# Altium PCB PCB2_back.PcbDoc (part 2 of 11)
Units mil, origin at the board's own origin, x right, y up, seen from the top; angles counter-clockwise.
Board outline 6299 x 3937 mil, 4 copper layers (TopLayer, GROUND, VCC, BottomLayer); 290 components, 470 nets, 2252 pads, 825 vias.
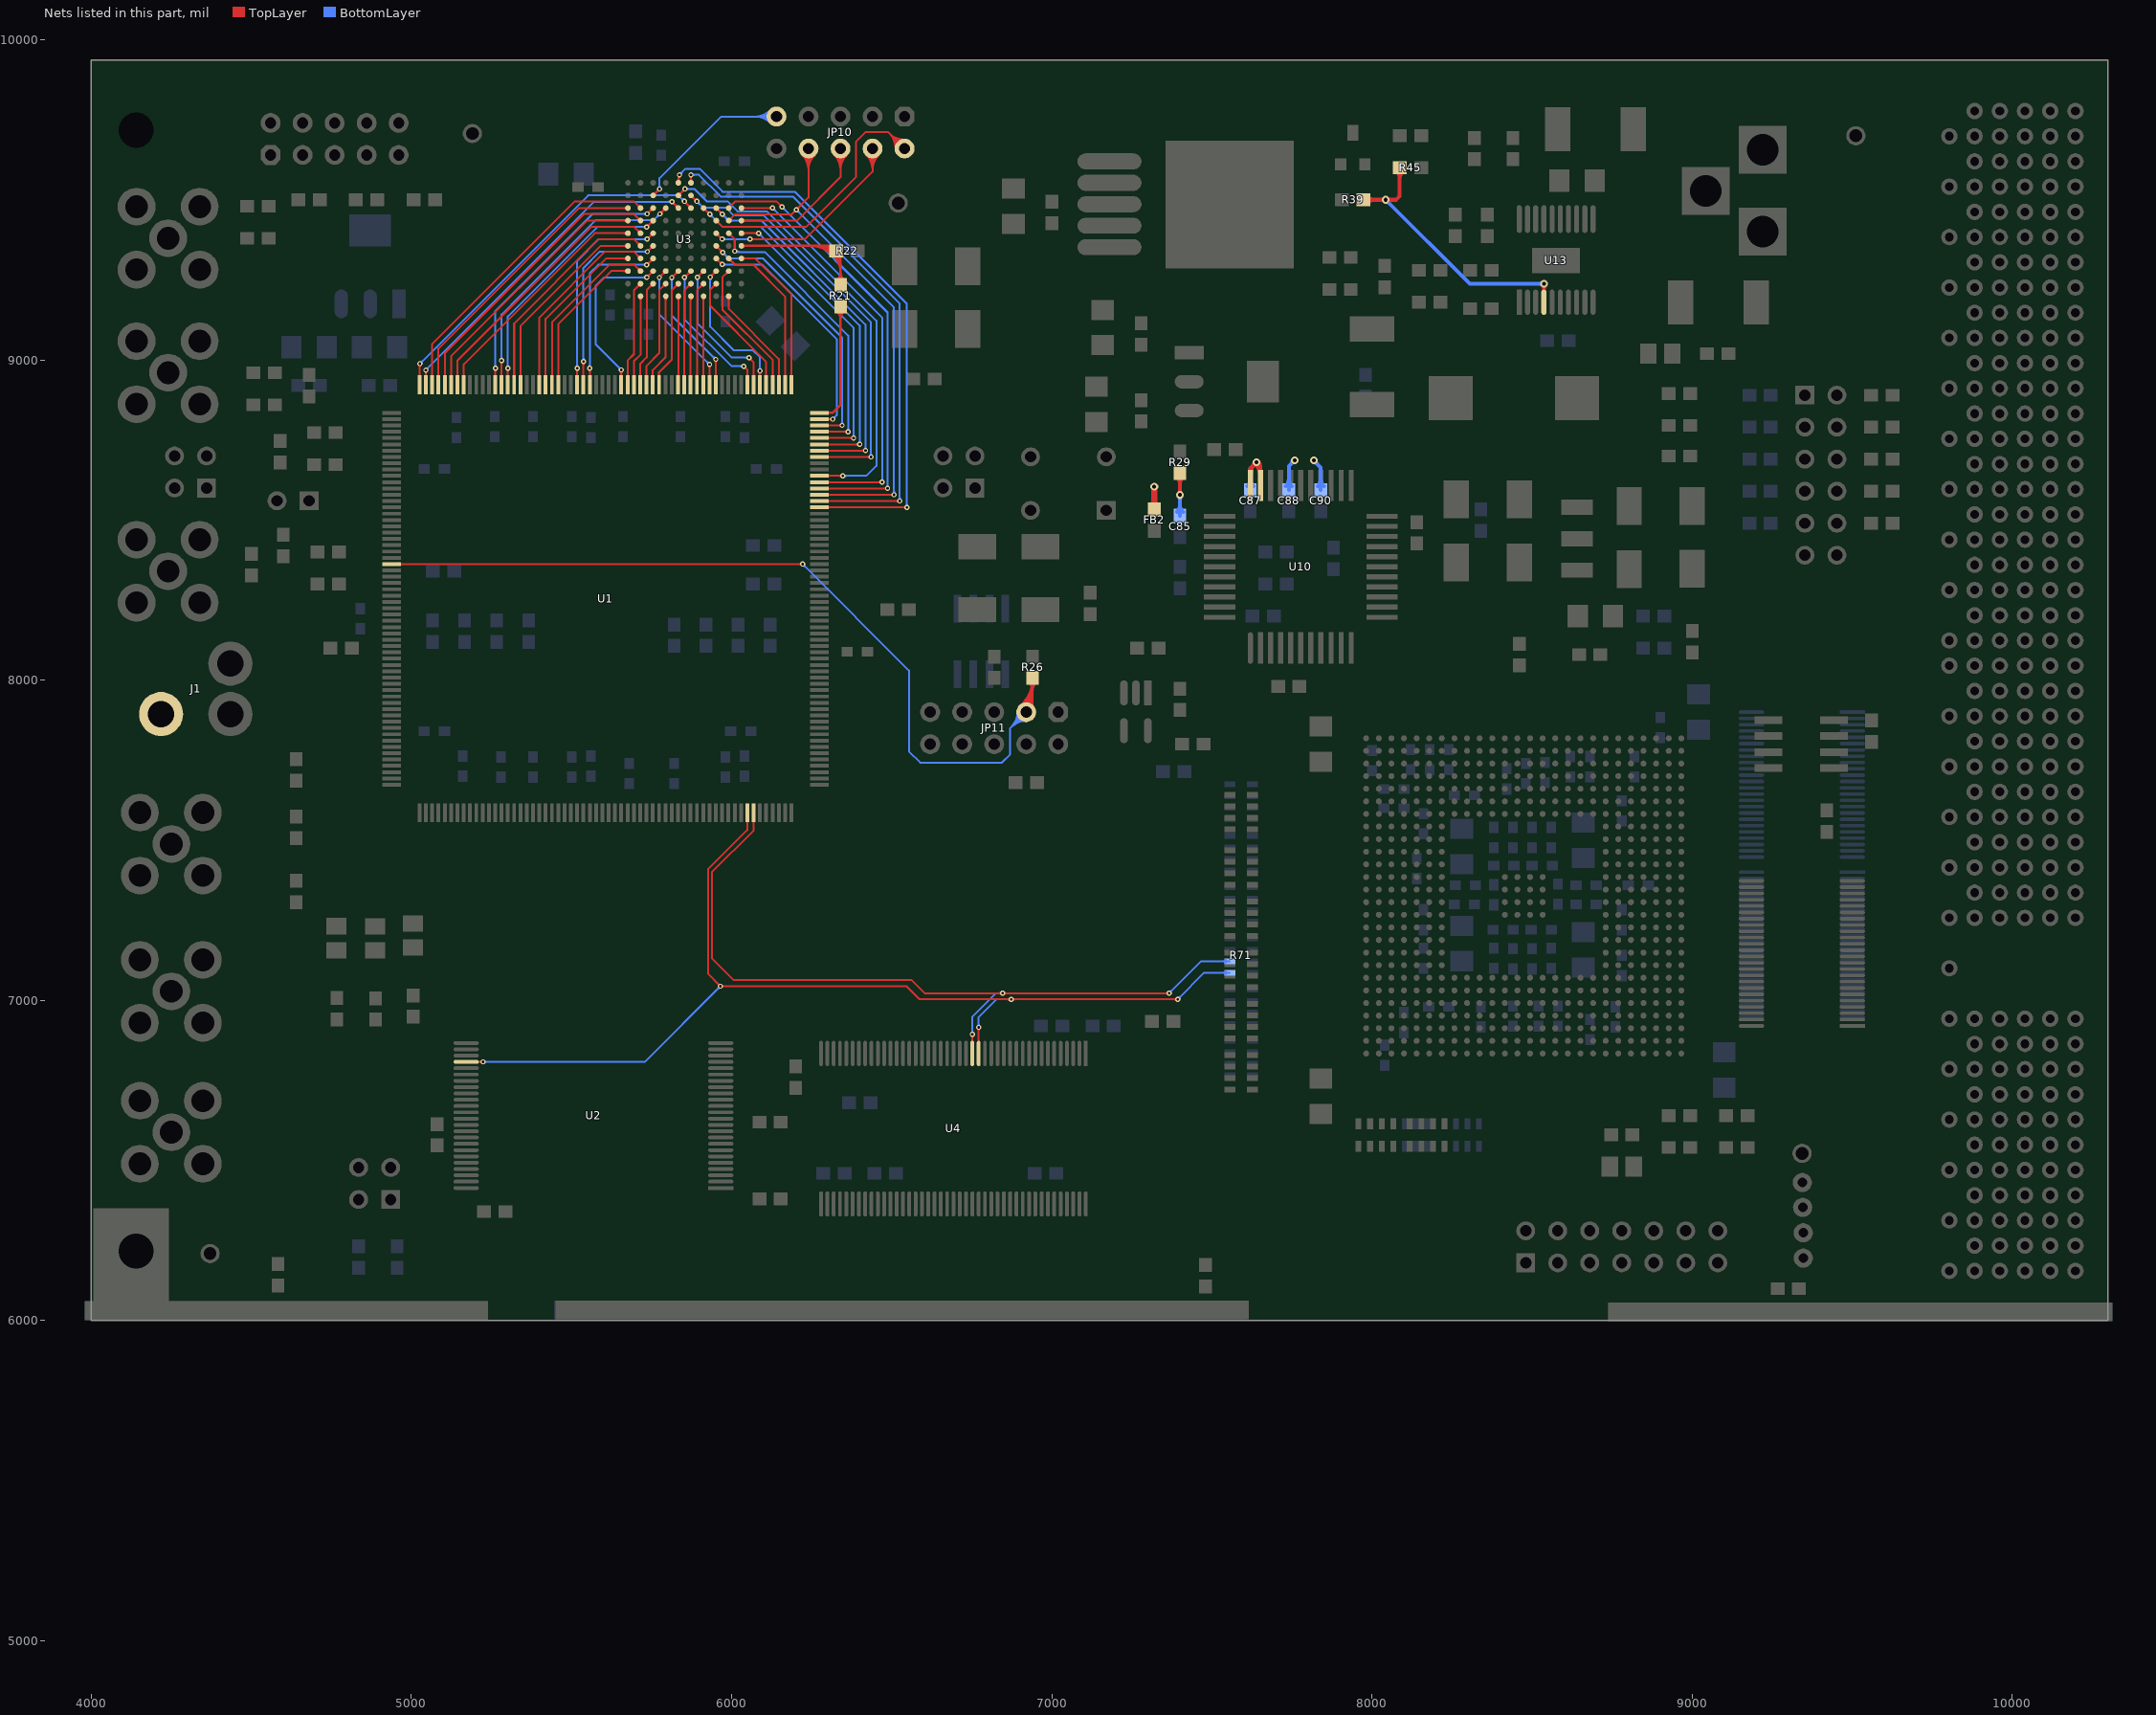
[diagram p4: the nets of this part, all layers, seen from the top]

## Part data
C1 C2 C3 C4 C5 C6 C7 C8 C9 C10 C11 C15 C16 C17 C18 C19 C22 C24 C25 C26 C27 C28 C32 C33 C34 C36 C37 C39 C40 C41 C42 C44 C45 C46 C47 C48 C49 C51 C52 C53 C54 C56 C57 C58 C59 C60 C61 C62 C63 C64 C65 C66 C67 C68 C69 C70 C71 C73 C74 C75 C76 C77 C79 C80 C81 C82 C83 C84 C85 C86 C87 C88 C89 C90 C91 C92 C93 C94 C95 C96 C97 C98 C99 C100 C101 C102 C103 C105 C107 C108 C109 C110 C111 C112 C113 C114 C115 C116 C117 C118 C119 C120 C121 C122 C123 C124 C125 C126 C127 C128 C129 C130 C131 C132 C133 C134 C136 C137 C139 C140 C141 C142 C143 C144 C145: "Capacitor"
C12 C13 C14 C23 C31 C35 C38 C43 C50 C72: "Polarized Capacitor (Radial)"
C20 C21 C29 C30 C55 C78 C104 C106 C135 C138 C146 C147: "Polarized Capacitor (Axial)"
DS1 DS2 DS3: "Typical RED, GREEN, YELLOW, AMBER GaAs LED"
DS4 DS5: "Typical BLUE SiC LED"
FB1 FB2 FB3 FB4 FB5 FB6 FB7 FB8: library part Inductor, "Inductor"
J1: "RCA Connector"
J2: library part "Header 7X2", "Header, 7-Pin, Dual row"
J4: "Z-Pack 2mm Hard Metric Type A 110 Position Female PCB Mount Connector"
J5: "Z-Pack 2mm Hard Metric Type B 110 Position Female Daughter Card Connector"
JP1 JP2 JP3 JP4 JP6 JP7 JP9: "Header, 2-Pin"
JP5 JP12: "Header, 2-Pin, Dual row"
JP8 JP10 JP11: library part "Header 5X2", "Header, 5-Pin, Dual row"
JP13: "Header, 6-Pin, Dual row"
L1: "Magnetic-Core Inductor"
Q1: library part QNPN, "NPN Bipolar Transistor"
R1 R2 R3 R4 R5 R6 R7 R8 R9 R10 R11 R12 R13 R14 R15 R16 R17 R18 R19 R20 R21 R22 R23 R24 R25 R26 R27 R28 R29 R30 R31 R38 R39 R41 R43 R44 R45 R46 R47 R48 R49 R50 R51 R52 R53 R54 R55 R56 R57 R58 R59 R60 R61 R62 R63 R64 R65 R66 R67 R68 R75 R76 R77 R80 R81 R82 R83 R84 R85 R86 R87: "Resistor"
R32 R33 R34 R35 R36 R37 R40 R42 R69 R70 R71 R72 R73 R74 R78 R79: "Resistor Array - Parts"
S1: "DIP Switch"
S2: "Switch"
U1: "Cyclone Family, 1.5V FPGA, 173 I/O Pins, 2 x PLLs, Commercial Grade, Speed Grade 6"
U3: "Hotlink II"
U4: "by TX"
U5 U6: library part Oscillator
U9 U18: library part "Volt Reg", "Voltage Regulator"
U14: library part "EMI filter"
U19: "EPCS1 Series, In-system programmable 3.3V configuration device, 8-Pin SOIC, 1-Megabit, Industrial Grade"

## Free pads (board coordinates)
  rect 236.22x314.96 smd: 0(4125,6193)
  round 50 hole 110: 1(4140,9717) 2(4140,6217)
  round 60 hole 30: 1(9344,6431) 2(9345,6353) 3(9347,6274) 4(9347,6195)
  round 60 hole 40: 5(4371,6209) 6(5190,9707) 7(9511,9700) 8(9343,6522) 9(6520,9490)
  rect 1259.84x59.06 smd: 10(4609,6031)
  rect 1259.84x59.05 smd far side: 10(4609,6031)
  rect 2165.35x59.05 smd far side: 11(6528,6033)
  rect 2165.35x59.05 smd: 11(6532,6033)
  rect 1574.8x59.05 smd: 12(9525,6027)
  rect 1574.8x59.05 smd far side: 12(9525,6027)

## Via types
v1: diameter 16, hole 8, TopLayer to BottomLayer, 408 vias
v2: diameter 20, hole 10, TopLayer to BottomLayer, 221 vias
v3: diameter 24, hole 12, TopLayer to BottomLayer, 194 vias
v4: diameter 56.69, hole 56.69, TopLayer to BottomLayer, 2 vias

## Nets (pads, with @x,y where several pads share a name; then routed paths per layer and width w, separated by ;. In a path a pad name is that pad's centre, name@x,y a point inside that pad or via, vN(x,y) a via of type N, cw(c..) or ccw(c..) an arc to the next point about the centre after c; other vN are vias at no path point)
1.4VPWRGD: R39.2 R45.2 U13.4 | length 1083.7
  TopLayer w12: R39.2@7973.46,9500 8075,9500 8086.54,9511.54 R45.2@8086.54,9600 ; R39.2@7985.11,9490.32 cw(c8008.47,9466.96) 8008.47,9500 cw(c8008.47,9533.04) R39.2@7985.11,9509.68 ; v3@8038.76,9495.76 ccw(c8028.51,9485.51) 8028.51,9500 ccw(c8028.51,9514.49) v3@8038.76,9504.24 ; v3@8047.24,9495.76 cw(c8057.49,9485.51) 8057.49,9500 cw(c8057.49,9514.49) v3@8047.24,9504.24 ; R45.2@8076.86,9590.32 cw(c8053.5,9566.96) 8086.54,9566.96 cw(c8119.57,9566.96) R45.2@8096.21,9590.32 ; v3@8532.53,9232.99 cw(c8522.29,9222.74) 8536.77,9222.74 cw(c8551.26,9222.74) v3@8541.01,9232.99 ; U13.4@8536.77,9180 v3(8536.77,9237.23)
  BottomLayer w12: v3@8043,9494 cw(c8043,9479.51) 8053.24,9489.76 cw(c8063.49,9500) v3@8049,9500 ; v3(8043,9500) 8305.77,9237.23 v3(8536.77,9237.23) ; v3@8532.53,9232.99 ccw(c8522.29,9222.74) 8522.29,9237.23 ccw(c8522.29,9251.71) v3@8532.53,9241.47
101_BISTLE: U1.113 U3.E1 | length 779.5
  TopLayer w6: U1.113@5161.03,8947.98 ccw(c5156.07,8952.94) 5163.09,8952.94 ccw(c5170.1,8952.94) U1.113@5165.14,8947.98 ; U1.113@5163.09,8922.31 5163.09,8986.09 5572.52,9395.52 U3.E1@5676,9395.52 ; U3.E1@5671.86,9391.38 ccw(c5661.86,9381.38) 5661.86,9395.52 ccw(c5661.86,9409.66) U3.E1@5671.86,9399.66
101_BOE0: U1.115 U3.D1 | length 849.6
  TopLayer w6: U1.115@5121.66,8947.98 ccw(c5116.7,8952.94) 5123.72,8952.94 ccw(c5130.73,8952.94) U1.115@5125.77,8947.98 ; U1.115@5123.72,8922.31 5123.72,9010.72 5547.89,9434.89 U3.D1@5676,9434.89 ; U3.D1@5671.86,9430.75 ccw(c5661.86,9420.75) 5661.86,9434.89 ccw(c5661.86,9449.03) U3.D1@5671.86,9439.03
101_BOE1: U1.116 U3.D2 | length 932.2
  TopLayer w6: U1.116@5101.98,8947.98 ccw(c5097.02,8952.94) 5104.03,8952.94 ccw(c5111.05,8952.94) U1.116@5106.09,8947.98 ; U1.116@5104.03,8922.31 5104.03,9021.03 5539,9456 5694.26,9456 U3.D2@5715.37,9434.89 ; U3.D2@5709.51,9434.89 ccw(c5695.37,9434.89) 5705.37,9444.89 ccw(c5715.37,9454.89) U3.D2@5715.37,9440.75
101_CLK: R21.1 R22.2 U3.F10 | length 830.3
  TopLayer w8: U3.F10@6030.33,9356.15 6310.39,9356.15 6340,9326.54 R21.1@6340,9233.46 ; U3.F10@6033.77,9352.71 cw(c6042.06,9344.42) 6042.06,9356.15 cw(c6042.06,9367.88) U3.F10@6033.77,9359.58 ; 6247.71,9356.15 cw(c6247.71,9263.14) R22.2@6313.48,9328.91 ; 6267.03,9356.15 cw(c6267.03,9282.46) R22.2@6319.13,9334.57 ; 6286.34,9356.15 cw(c6286.34,9301.77) R22.2@6324.79,9340.22 ; R22.2@6305.65,9356.15 cw(c6305.65,9321.09) R22.2@6330.45,9345.88 ; R22.2@6317.41,9328.91 cw(c6262.88,9274.38) 6340,9274.38 ; R22.2@6323.07,9334.57 cw(c6282.2,9293.69) 6340,9293.69 ; R22.2@6328.73,9340.22 cw(c6301.51,9313.01) 6340,9313.01 ; R21.1@6328.91,9246.52 ccw(c6302.13,9273.3) 6340,9273.3 ccw(c6377.87,9273.3) R21.1@6351.09,9246.52
101_DECOMDE: U1.114 U3.E2 | length 861.3
  TopLayer w6: U1.114@5141.35,8947.98 ccw(c5136.39,8952.94) 5143.4,8952.94 ccw(c5150.42,8952.94) U1.114@5145.46,8947.98 ; U1.114@5143.4,8922.31 5143.4,8997.4 5561,9415 5695.89,9415 U3.E2@5715.37,9395.52 ; U3.E2@5709.51,9395.52 ccw(c5695.37,9395.52) 5705.37,9405.52 ccw(c5715.37,9415.52) U3.E2@5715.37,9401.38
101_FRAMCHAR: U1.106 U3.D3 | length 900.4
  TopLayer w6: v1@5297.35,8970.35 cw(c5288.81,8961.81) 5300.88,8961.81 cw(c5312.95,8961.81) v1@5304.42,8970.35 ; U1.106@5298.83,8947.98 ccw(c5293.87,8952.94) 5300.88,8952.94 ccw(c5307.9,8952.94) U1.106@5302.94,8947.98 ; U1.106@5300.88,8922.31 v1(5300.88,8973.88) ; v1(5734.85,9415) U3.D3@5754.74,9434.89 ; v1@5734.85,9420 ccw(c5734.85,9432.07) 5743.39,9423.54 ccw(c5751.92,9415) v1@5739.85,9415 ; U3.D3@5748.88,9434.89 cw(c5734.74,9434.89) 5744.74,9424.89 cw(c5754.74,9414.89) U3.D3@5754.74,9429.03
  BottomLayer w6: v1@5297.35,8977.42 ccw(c5288.81,8985.95) 5300.88,8985.95 ccw(c5312.95,8985.95) v1@5304.42,8977.42 ; v1(5300.88,8973.88) 5300.88,9135.88 5580,9415 v1(5734.85,9415) ; v1@5731.31,9411.46 ccw(c5722.78,9402.93) 5722.78,9415 ccw(c5722.78,9427.07) v1@5731.31,9418.54
101_INSEL: U1.49 U3.C10 | length 1400
  TopLayer w6: U3.C10@6030.33,9474.26 v1(6127.74,9474.26) ; U3.C10@6034.47,9470.12 cw(c6044.47,9460.12) 6044.47,9474.26 cw(c6044.47,9488.4) U3.C10@6034.47,9478.4 ; v1@6124.2,9470.72 ccw(c6115.67,9462.19) 6115.67,9474.26 ccw(c6115.67,9486.33) v1@6124.2,9477.8 ; U1.49@6274.31,8618.17 v1(6470,8618.17) ; U1.49@6299.98,8616.12 cw(c6304.94,8611.16) 6304.94,8618.17 cw(c6304.94,8625.19) U1.49@6299.98,8620.23 ; v1@6466.46,8614.64 ccw(c6457.93,8606.1) 6457.93,8618.17 ccw(c6457.93,8630.24) v1@6466.46,8621.71
  BottomLayer w6: v1@6127.74,9469.26 cw(c6127.74,9457.19) 6136.28,9465.72 cw(c6144.81,9474.26) v1@6132.74,9474.26 ; v1(6127.74,9474.26) 6470,9132 v1(6470,8618.17) ; v1@6466.46,8621.71 ccw(c6457.93,8630.24) 6470,8630.24 ccw(c6482.07,8630.24) v1@6473.54,8621.71
101_L\F\I\: U1.74 U3.H4 | length 537.5
  TopLayer w6: v1(5774,9257.3) U3.H4@5794.11,9277.41 ; v1@5774,9262.3 ccw(c5774,9274.37) 5782.54,9265.83 ccw(c5791.07,9257.3) v1@5779,9257.3 ; U3.H4@5788.25,9277.41 cw(c5774.11,9277.41) 5784.11,9267.41 cw(c5794.11,9257.41) U3.H4@5794.11,9271.55 ; v1@5927.27,8982.66 cw(c5918.73,8974.13) 5930.8,8974.13 cw(c5942.87,8974.13) v1@5934.34,8982.66 ; U1.74@5928.75,8947.98 ccw(c5923.79,8952.94) 5930.8,8952.94 ccw(c5937.82,8952.94) U1.74@5932.86,8947.98 ; U1.74@5930.8,8922.31 v1(5930.8,8986.2)
  BottomLayer w6: v1@5770.46,9253.76 cw(c5761.93,9245.23) 5774,9245.23 cw(c5786.07,9245.23) v1@5777.54,9253.76 ; v1(5774,9257.3) 5774,9143 v1(5930.8,8986.2) ; v1@5925.8,8986.2 ccw(c5913.73,8986.2) 5922.27,8994.73 ccw(c5930.8,9003.27) v1@5930.8,8991.2
101_LPEN: U1.118 U3.C2 | length 1004.4
  TopLayer w6: U1.118@5062.61,8947.98 ccw(c5057.65,8952.94) 5064.66,8952.94 ccw(c5071.68,8952.94) U1.118@5066.72,8947.98 ; U1.118@5064.66,8922.31 5064.66,9049.66 5510,9495 5694.63,9495 U3.C2@5715.37,9474.26 ; U3.C2@5709.51,9474.26 ccw(c5695.37,9474.26) 5705.37,9484.26 ccw(c5715.37,9494.26) U3.C2@5715.37,9480.12
101_OELE: U1.95 U3.E3 | length 769.2
  TopLayer w6: v1@5513.88,8970.88 cw(c5505.35,8962.35) 5517.42,8962.35 cw(c5529.49,8962.35) v1@5520.95,8970.88 ; U1.95@5515.36,8947.98 ccw(c5510.4,8952.94) 5517.42,8952.94 ccw(c5524.43,8952.94) U1.95@5519.47,8947.98 ; U1.95@5517.42,8922.31 v1(5517.42,8974.42) ; v1(5736.22,9377) U3.E3@5754.74,9395.52 ; v1@5736.22,9382 ccw(c5736.22,9394.07) 5744.76,9385.54 ccw(c5753.29,9377) v1@5741.22,9377 ; U3.E3@5748.88,9395.52 cw(c5734.74,9395.52) 5744.74,9385.52 cw(c5754.74,9375.52) U3.E3@5754.74,9389.66
  BottomLayer w6: v1@5513.88,8977.95 ccw(c5505.35,8986.49) 5517.42,8986.49 ccw(c5529.49,8986.49) v1@5520.95,8977.95 ; v1(5517.42,8974.42) 5517.42,9309.42 5585,9377 v1(5736.22,9377) ; v1@5732.69,9373.46 ccw(c5724.15,9364.93) 5724.15,9377 ccw(c5724.15,9389.07) v1@5732.69,9380.54
101_PARCTL: U1.54 U3.C8 | length 1263.5
  TopLayer w6: U3.C8@5951.59,9468.4 cw(c5951.59,9454.26) 5961.59,9464.26 cw(c5971.59,9474.26) U3.C8@5957.45,9474.26 ; U3.C8@5951.59,9474.26 v1(5970.85,9455) ; v1@5965.85,9455 ccw(c5953.78,9455) 5962.31,9463.54 ccw(c5970.85,9472.07) v1@5970.85,9460 ; U1.54@6274.31,8716.6 v1(6418,8716.6) ; U1.54@6299.98,8714.54 cw(c6304.94,8709.58) 6304.94,8716.6 cw(c6304.94,8723.61) U1.54@6299.98,8718.65 ; v1@6414.46,8713.06 ccw(c6405.93,8704.53) 6405.93,8716.6 ccw(c6405.93,8728.67) v1@6414.46,8720.13
  BottomLayer w6: v1@5970.85,9450 cw(c5970.85,9437.93) 5979.39,9446.46 cw(c5987.92,9455) v1@5975.85,9455 ; v1(5970.85,9455) 5990.85,9435 6093,9435 6418,9110 v1(6418,8716.6) ; v1@6414.46,8720.13 ccw(c6405.93,8728.67) 6418,8728.67 ccw(c6430.07,8728.67) v1@6421.54,8720.13
101_REFCLK+: R21.2 U1.60 | length 442.2
  TopLayer w8: U1.60@6274.31,8834.71 6314.71,8834.71 6340,8860 R21.2@6340,9166.54 ; R21.2@6328.91,9153.48 cw(c6302.13,9126.7) 6340,9126.7 cw(c6377.87,9126.7) R21.2@6351.09,9153.48
101_RFEN: U1.117 U3.C1 | length 919.7
  TopLayer w6: U1.117@5082.29,8947.98 ccw(c5077.33,8952.94) 5084.35,8952.94 ccw(c5091.36,8952.94) U1.117@5086.4,8947.98 ; U1.117@5084.35,8922.31 5084.35,9035.35 5523.26,9474.26 U3.C1@5676,9474.26 ; U3.C1@5671.86,9470.12 ccw(c5661.86,9460.12) 5661.86,9474.26 ccw(c5661.86,9488.4) U3.C1@5671.86,9478.4
101_RFMODE: U1.48 U3.C9 | length 1519.6
  TopLayer w6: U3.C9@5990.96,9474.26 6011.7,9495 6140,9495 v1(6157,9478) ; U3.C9@5990.96,9480.12 ccw(c5990.96,9494.26) 6000.96,9484.26 ccw(c6010.96,9474.26) U3.C9@5996.82,9474.26 ; v1@6152,9478 ccw(c6139.93,9478) 6148.46,9486.54 ccw(c6157,9495.07) v1@6157,9483 ; U1.48@6274.31,8598.49 v1(6487,8598.49) ; U1.48@6299.98,8596.43 cw(c6304.94,8591.47) 6304.94,8598.49 cw(c6304.94,8605.5) U1.48@6299.98,8600.54 ; v1@6483.46,8594.95 ccw(c6474.93,8586.42) 6474.93,8598.49 ccw(c6474.93,8610.56) v1@6483.46,8602.02
  BottomLayer w6: v1@6157,9473 cw(c6157,9460.93) 6165.54,9469.46 cw(c6174.07,9478) v1@6162,9478 ; v1(6157,9478) 6487,9148 v1(6487,8598.49) ; v1@6483.46,8602.02 ccw(c6474.93,8610.56) 6487,8610.56 ccw(c6499.07,8610.56) v1@6490.54,8602.02
101_RXCKSEL: U1.57 U3.E9 | length 1023.7
  TopLayer w6: U3.E9@5990.96,9389.66 cw(c5990.96,9375.52) 6000.96,9385.52 cw(c6010.96,9395.52) U3.E9@5996.82,9395.52 ; U3.E9@5990.96,9395.52 6009.48,9377 v1(6009.48,9339.52) ; v1@6005.94,9343.06 ccw(c5997.41,9351.59) 6009.48,9351.59 ccw(c6021.55,9351.59) v1@6013.02,9343.06 ; U1.57@6274.31,8775.65 v1(6364,8775.65) ; U1.57@6299.98,8773.6 cw(c6304.94,8768.64) 6304.94,8775.65 cw(c6304.94,8782.67) U1.57@6299.98,8777.71 ; v1@6360.46,8772.12 ccw(c6351.93,8763.58) 6351.93,8775.65 ccw(c6351.93,8787.72) v1@6360.46,8779.19
  BottomLayer w6: v1(6009.48,9339.52) 6012,9337 6103,9337 6364,9076 v1(6364,8775.65) ; v1@6013.02,9343.06 ccw(c6027.63,9357.67) 6027.63,9337 ; v1@6360.46,8779.19 ccw(c6351.93,8787.72) 6364,8787.72 ccw(c6376.07,8787.72) v1@6367.54,8779.19
101_RXCLK+: U1.83 U3.K4 | length 326.4
  TopLayer w6: U1.83@5751.58,8947.98 ccw(c5746.62,8952.94) 5753.64,8952.94 ccw(c5760.65,8952.94) U1.83@5755.69,8947.98 ; U1.83@5753.64,8922.31 5753.64,8968.64 5794.11,9009.11 U3.K4@5794.11,9198.67 ; U3.K4@5789.97,9194.53 cw(c5779.97,9184.53) 5794.11,9184.53 cw(c5808.25,9184.53) U3.K4@5798.25,9194.53
101_RXCLK-: U1.84 U3.J4 | length 373.9
  TopLayer w6: U1.84@5731.9,8947.98 ccw(c5726.94,8952.94) 5733.95,8952.94 ccw(c5740.97,8952.94) U1.84@5736.01,8947.98 ; U1.84@5733.95,8922.31 5733.95,8980.95 5774,9021 5774,9217.93 U3.J4@5794.11,9238.04 ; U3.J4@5788.25,9238.04 cw(c5774.11,9238.04) 5784.11,9228.04 cw(c5794.11,9218.04) U3.J4@5794.11,9232.18
101_RXCLKC+: U1.107 U3.C4 | length 979.3
  TopLayer w6: v1@5277.66,8994.78 cw(c5269.13,8986.24) 5281.2,8986.24 cw(c5293.27,8986.24) v1@5284.73,8994.78 ; U1.107@5279.14,8947.98 ccw(c5274.18,8952.94) 5281.2,8952.94 ccw(c5288.21,8952.94) U1.107@5283.25,8947.98 ; U1.107@5281.2,8922.31 v1(5281.2,8998.32) ; v1(5775.85,9456) U3.C4@5794.11,9474.26 ; v1@5775.85,9461 ccw(c5775.85,9473.07) 5784.39,9464.54 ccw(c5792.92,9456) v1@5780.85,9456 ; U3.C4@5788.25,9474.26 cw(c5774.11,9474.26) 5784.11,9464.26 cw(c5794.11,9454.26) U3.C4@5794.11,9468.4
  BottomLayer w6: v1@5277.66,9001.85 ccw(c5269.13,9010.39) 5281.2,9010.39 ccw(c5293.27,9010.39) v1@5284.73,9001.85 ; v1(5281.2,8998.32) 5281.2,9142 5340.59,9201.39 5575.2,9436 5755.85,9436 v1(5775.85,9456) ; v1@5770.85,9456 cw(c5758.78,9456) 5767.31,9447.46 cw(c5775.85,9438.93) v1@5775.85,9451
101_RXD0: U1.98 U3.H1 | length 508.7
  TopLayer w6: U1.98@5456.31,8947.98 ccw(c5451.35,8952.94) 5458.36,8952.94 ccw(c5465.38,8952.94) U1.98@5460.42,8947.98 ; U1.98@5458.36,8922.31 5458.36,9111.36 5624.41,9277.41 U3.H1@5676,9277.41 ; U3.H1@5671.86,9273.27 ccw(c5661.86,9263.27) 5661.86,9277.41 ccw(c5661.86,9291.55) U3.H1@5671.86,9281.55
101_RXD1: U1.101 U3.G2 | length 653.3
  TopLayer w6: U1.101@5397.25,8947.98 ccw(c5392.29,8952.94) 5399.31,8952.94 ccw(c5406.32,8952.94) U1.101@5401.36,8947.98 ; U1.101@5399.31,8922.31 5399.31,9132.31 5605,9338 5694.15,9338 U3.G2@5715.37,9316.78 ; U3.G2@5709.51,9316.78 ccw(c5695.37,9316.78) 5705.37,9326.78 ccw(c5715.37,9336.78) U3.G2@5715.37,9322.64
101_RXD2: U1.99 U3.H2 | length 587.7
  TopLayer w6: U1.99@5436.62,8947.98 ccw(c5431.66,8952.94) 5438.68,8952.94 ccw(c5445.69,8952.94) U1.99@5440.73,8947.98 ; U1.99@5438.68,8922.31 5438.68,9117.68 5618,9297 5695.78,9297 U3.H2@5715.37,9277.41 ; U3.H2@5709.51,9277.41 ccw(c5695.37,9277.41) 5705.37,9287.41 ccw(c5715.37,9297.41) U3.H2@5715.37,9283.27
101_RXD3: U1.87 U3.J2 | length 365.7
  TopLayer w6: U1.87@5672.84,8947.98 ccw(c5667.88,8952.94) 5674.9,8952.94 ccw(c5681.91,8952.94) U1.87@5676.95,8947.98 ; U1.87@5674.9,8922.31 5674.9,8997.9 5695,9018 5695,9217.67 U3.J2@5715.37,9238.04 ; U3.J2@5709.51,9238.04 cw(c5695.37,9238.04) 5705.37,9228.04 cw(c5715.37,9218.04) U3.J2@5715.37,9232.18
101_RXD4: U1.86 U3.K2 | length 318.2
  TopLayer w6: U1.86@5692.53,8947.98 ccw(c5687.57,8952.94) 5694.58,8952.94 ccw(c5701.6,8952.94) U1.86@5696.64,8947.98 ; U1.86@5694.58,8922.31 5694.58,8995.58 5715.37,9016.37 U3.K2@5715.37,9198.67 ; U3.K2@5711.23,9194.53 cw(c5701.23,9184.53) 5715.37,9184.53 cw(c5729.51,9184.53) U3.K2@5719.51,9194.53
101_RXD5: U1.93 U3.G3 | length 674.6
  TopLayer w6: v1@5553.25,8970.25 cw(c5544.72,8961.72) 5556.79,8961.72 cw(c5568.86,8961.72) v1@5560.32,8970.25 ; U1.93@5554.73,8947.98 ccw(c5549.77,8952.94) 5556.79,8952.94 ccw(c5563.8,8952.94) U1.93@5558.84,8947.98 ; U1.93@5556.79,8922.31 v1(5556.79,8973.79) ; v1(5734.96,9297) U3.G3@5754.74,9316.78 ; v1@5734.96,9302 ccw(c5734.96,9314.07) 5743.5,9305.54 ccw(c5752.03,9297) v1@5739.96,9297 ; U3.G3@5748.88,9316.78 cw(c5734.74,9316.78) 5744.74,9306.78 cw(c5754.74,9296.78) U3.G3@5754.74,9310.92
  BottomLayer w6: v1@5553.25,8977.32 ccw(c5544.72,8985.86) 5556.79,8985.86 ccw(c5568.86,8985.86) v1@5560.32,8977.32 ; v1(5556.79,8973.79) 5556.79,9270.79 5583,9297 v1(5734.96,9297) ; v1@5731.43,9293.46 ccw(c5722.89,9284.93) 5722.89,9297 ccw(c5722.89,9309.07) v1@5731.43,9300.54
101_RXD6: U1.88 U3.H3 | length 649.1
  TopLayer w6: v1@5651.68,8965.25 cw(c5643.14,8956.72) 5655.21,8956.72 cw(c5667.28,8956.72) v1@5658.75,8965.25 ; U1.88@5653.16,8947.98 ccw(c5648.2,8952.94) 5655.21,8952.94 ccw(c5662.23,8952.94) U1.88@5657.27,8947.98 ; U1.88@5655.21,8922.31 v1(5655.21,8968.79) ; v1(5735,9257.67) U3.H3@5754.74,9277.41 ; v1@5735,9262.67 ccw(c5735,9274.74) 5743.54,9266.2 ccw(c5752.07,9257.67) v1@5740,9257.67 ; U3.H3@5748.88,9277.41 cw(c5734.74,9277.41) 5744.74,9267.41 cw(c5754.74,9257.41) U3.H3@5754.74,9271.55
  BottomLayer w6: v1@5650.21,8968.79 ccw(c5638.14,8968.79) 5646.68,8977.32 ccw(c5655.21,8985.86) v1@5655.21,8973.79 ; v1(5655.21,8968.79) 5576,9048 5576,9232 5601.67,9257.67 v1(5735,9257.67) ; v1@5731.46,9254.13 ccw(c5722.93,9245.6) 5722.93,9257.67 ccw(c5722.93,9269.74) v1@5731.46,9261.2
101_RXD7: U1.85 U3.J3 | length 365.7
  TopLayer w6: U1.85@5712.21,8947.98 ccw(c5707.25,8952.94) 5714.27,8952.94 ccw(c5721.28,8952.94) U1.85@5716.32,8947.98 ; U1.85@5714.27,8922.31 5714.27,8987.27 5735,9008 5735,9218.3 U3.J3@5754.74,9238.04 ; U3.J3@5748.88,9238.04 cw(c5734.74,9238.04) 5744.74,9228.04 cw(c5754.74,9218.04) U3.J3@5754.74,9232.18
101_RXLE: U1.108 U3.C3 | length 961.6
  TopLayer w6: v1@5258.46,8970.46 cw(c5249.93,8961.93) 5262,8961.93 cw(c5274.07,8961.93) v1@5265.54,8970.46 ; U1.108@5259.46,8947.98 ccw(c5253.32,8954.12) 5262,8954.12 ; U1.108@5261.51,8922.31 5262,8922.8 v1(5262,8974) ; v1(5736.48,9456) U3.C3@5754.74,9474.26 ; v1@5736.48,9461 ccw(c5736.48,9473.07) 5745.02,9464.54 ccw(c5753.55,9456) v1@5741.48,9456 ; U3.C3@5748.88,9474.26 cw(c5734.74,9474.26) 5744.74,9464.26 cw(c5754.74,9454.26) U3.C3@5754.74,9468.4
  BottomLayer w6: v1@5258.46,8977.54 ccw(c5249.93,8986.07) 5262,8986.07 ccw(c5274.07,8986.07) v1@5265.54,8977.54 ; v1(5262,8974) 5262,9153 5565,9456 v1(5736.48,9456) ; v1@5732.94,9452.46 ccw(c5724.41,9443.93) 5724.41,9456 ccw(c5724.41,9468.07) v1@5732.94,9459.54
101_RXMODE: U1.45 U3.A5 | length 1936.4
  TopLayer w6: U3.A5@5829.34,9557.14 ccw(c5819.34,9567.14) 5833.48,9567.14 ccw(c5847.62,9567.14) U3.A5@5837.62,9557.14 ; U3.A5@5833.48,9553 5833.48,9574.48 v1(5837,9578) ; U3.A5@5833.48,9557.43 cw(c5857.57,9557.43) v1@5840.54,9574.46 ; U1.45@6274.31,8539.43 v1(6547,8539.43) ; U1.45@6299.98,8537.38 cw(c6304.94,8532.42) 6304.94,8539.43 cw(c6304.94,8546.45) U1.45@6299.98,8541.49 ; v1@6543.46,8535.9 ccw(c6534.93,8527.36) 6534.93,8539.43 ccw(c6534.93,8551.5) v1@6543.46,8542.97
  BottomLayer w6: v1(5837,9578) 5856,9597 5900,9597 5972,9525 6197,9525 6547,9175 v1(6547,8539.43) ; v1@5837,9583 ccw(c5837,9595.07) 5845.54,9586.54 ccw(c5854.07,9578) v1@5842,9578 ; v1@6543.46,8542.97 ccw(c6534.93,8551.5) 6547,8551.5 ccw(c6559.07,8551.5) v1@6550.54,8542.97
101_RXOP: U1.100 U3.G1 | length 574.1
  TopLayer w6: U1.100@5416.94,8947.98 ccw(c5411.98,8952.94) 5418.99,8952.94 ccw(c5426.01,8952.94) U1.100@5421.05,8947.98 ; U1.100@5418.99,8922.31 5418.99,9127.99 5607.78,9316.78 U3.G1@5676,9316.78 ; U3.G1@5671.86,9312.64 ccw(c5661.86,9302.64) 5661.86,9316.78 ccw(c5661.86,9330.92) U3.G1@5671.86,9320.92
101_RXRATE: U1.119 U3.C5 | length 1168.9
  TopLayer w6: v1@5041.44,8964.44 cw(c5032.91,8955.91) 5044.98,8955.91 cw(c5057.05,8955.91) v1@5048.51,8964.44 ; U1.119@5042.92,8947.98 ccw(c5037.96,8952.94) 5044.98,8952.94 ccw(c5051.99,8952.94) U1.119@5047.03,8947.98 ; U1.119@5044.98,8922.31 v1(5044.98,8967.98) ; v1@5813.74,9489 cw(c5813.74,9476.93) 5822.28,9485.46 cw(c5830.81,9494) v1@5818.74,9494 ; v1(5813.74,9494) U3.C5@5833.48,9474.26 ; U3.C5@5827.62,9474.26 ccw(c5813.48,9474.26) 5823.48,9484.26 ccw(c5833.48,9494.26) U3.C5@5833.48,9480.12
  BottomLayer w6: v1@5044.98,8968.98 5570,9494 v1(5813.74,9494) ; v1@5044.98,8972.98 ccw(c5044.98,8982.63) 5051.8,8975.8 ; v1@5049.98,8967.98 cw(c5064.46,8967.98) 5054.22,8978.22 ; v1@5810.2,9490.46 ccw(c5801.67,9481.93) 5801.67,9494 ccw(c5801.67,9506.07) v1@5810.2,9497.54
101_RXST0: U1.94 U3.F3 | length 720.1
  TopLayer w6: v1@5533.57,8991.57 cw(c5525.03,8983.03) 5537.1,8983.03 cw(c5549.17,8983.03) v1@5540.64,8991.57 ; U1.94@5535.05,8947.98 ccw(c5530.09,8952.94) 5537.1,8952.94 ccw(c5544.12,8952.94) U1.94@5539.16,8947.98 ; U1.94@5537.1,8922.31 v1(5537.1,8995.1) ; v1(5736.59,9338) U3.F3@5754.74,9356.15 ; v1@5736.59,9343 ccw(c5736.59,9355.07) 5745.13,9346.54 ccw(c5753.66,9338) v1@5741.59,9338 ; U3.F3@5748.88,9356.15 cw(c5734.74,9356.15) 5744.74,9346.15 cw(c5754.74,9336.15) U3.F3@5754.74,9350.29
  BottomLayer w6: v1@5533.57,8998.64 ccw(c5525.03,9007.17) 5537.1,9007.17 ccw(c5549.17,9007.17) v1@5540.64,8998.64 ; v1(5537.1,8995.1) 5537.1,9287.1 5588,9338 v1(5736.59,9338) ; v1@5733.06,9334.46 ccw(c5724.52,9325.93) 5724.52,9338 ccw(c5724.52,9350.07) v1@5733.06,9341.54
101_RXST1: U1.105 U3.F2 | length 737.1
  TopLayer w6: U1.105@5318.51,8947.98 ccw(c5313.55,8952.94) 5320.57,8952.94 ccw(c5327.58,8952.94) U1.105@5322.62,8947.98 ; U1.105@5320.57,8922.31 5320.57,9113.57 5584,9377 5694.52,9377 U3.F2@5715.37,9356.15 ; U3.F2@5709.51,9356.15 ccw(c5695.37,9356.15) 5705.37,9366.15 ccw(c5715.37,9376.15) U3.F2@5715.37,9362.01
101_RXST2: U1.104 U3.F1 | length 655.9
  TopLayer w6: U1.104@5338.2,8947.98 ccw(c5333.24,8952.94) 5340.25,8952.94 ccw(c5347.27,8952.94) U1.104@5342.31,8947.98 ; U1.104@5340.25,8922.31 5340.25,9105.25 5591.15,9356.15 U3.F1@5676,9356.15 ; U3.F1@5671.86,9352.01 ccw(c5661.86,9342.01) 5661.86,9356.15 ccw(c5661.86,9370.29) U3.F1@5671.86,9360.29
101_SCSEL: U1.63 U3.K9 | length 374.4
  TopLayer w6: U3.K9@5986.82,9194.53 cw(c5976.82,9184.53) 5990.96,9184.53 cw(c6005.1,9184.53) U3.K9@5995.1,9194.53 ; U3.K9@5990.96,9198.67 5990.96,9159.04 6147.34,9002.66 U1.63@6147.34,8922.31 ; U1.63@6145.28,8947.98 ccw(c6140.32,8952.94) 6147.34,8952.94 ccw(c6154.35,8952.94) U1.63@6149.39,8947.98
101_SDASEL: U1.120 U3.C6 | length 1252.6
  TopLayer w6: v1@5022.46,8984.46 cw(c5013.93,8975.93) 5026,8975.93 cw(c5038.07,8975.93) v1@5029.54,8984.46 ; U1.120@5023.24,8947.98 ccw(c5016.57,8954.65) 5026,8954.65 ; U1.120@5025.29,8922.31 5026,8923.02 v1(5026,8988) ; v1@5852.11,9490 cw(c5852.11,9477.93) 5860.65,9486.46 cw(c5869.18,9495) v1@5857.11,9495 ; v1(5852.11,9495) U3.C6@5872.85,9474.26 ; U3.C6@5866.99,9474.26 ccw(c5852.85,9474.26) 5862.85,9484.26 ccw(c5872.85,9494.26) U3.C6@5872.85,9480.12
  BottomLayer w6: v1(5026,8988) 5552,9514 5833.11,9514 v1(5852.11,9495) ; v1@5026,8993 ccw(c5026,9005.07) 5034.54,8996.54 ccw(c5043.07,8988) v1@5031,8988 ; v1@5847.11,9495 ccw(c5835.04,9495) 5843.57,9503.54 ccw(c5852.11,9512.07) v1@5852.11,9500
101_SPDSEL: U1.55 U3.C7 | length 1245.4
  TopLayer w6: U3.C7@5912.22,9468.4 cw(c5912.22,9454.26) 5922.22,9464.26 cw(c5932.22,9474.26) U3.C7@5918.08,9474.26 ; U3.C7@5912.22,9474.26 v1(5931.48,9455) ; v1@5926.48,9455 ccw(c5914.41,9455) 5922.94,9463.54 ccw(c5931.48,9472.07) v1@5931.48,9460 ; U1.55@6274.31,8736.28 v1(6400,8736.28) ; U1.55@6299.98,8734.23 cw(c6304.94,8729.27) 6304.94,8736.28 cw(c6304.94,8743.3) U1.55@6299.98,8738.34 ; v1@6396.46,8732.75 ccw(c6387.93,8724.21) 6387.93,8736.28 ccw(c6387.93,8748.35) v1@6396.46,8739.82
  BottomLayer w6: v1@5931.48,9450 cw(c5931.48,9437.93) 5940.02,9446.46 cw(c5948.55,9455) v1@5936.48,9455 ; v1(5931.48,9455) 5971.48,9415 6092,9415 6400,9107 v1(6400,8736.28) ; v1@6396.46,8739.82 ccw(c6387.93,8748.35) 6400,8748.35 ccw(c6412.07,8748.35) v1@6403.54,8739.82
101_T\R\S\T\Z\: JP10.8 U1.47 U3.D9 | length 2059
  TopLayer w6: U3.D9@5990.96,9434.89 6011.07,9455 6188,9455 6240,9507 JP10.8@6240,9660 ; U3.D9@5990.96,9440.75 ccw(c5990.96,9454.89) 6000.96,9444.89 ccw(c6010.96,9434.89) U3.D9@5996.82,9434.89 ; v1@6197,9469 cw(c6184.93,9469) 6193.46,9460.46 cw(c6202,9451.93) v1@6202,9464 ; v1@6202,9474 ccw(c6202,9486.07) 6210.54,9477.54 ccw(c6219.07,9469) v1@6207,9469 ; JP10.8@6220.2,9640.2 cw(c6172.4,9592.4) 6240,9592.4 cw(c6307.6,9592.4) JP10.8@6259.8,9640.2 ; JP10.8@6224.44,9644.44 cw(c6186.89,9606.89) 6240,9606.89 cw(c6293.11,9606.89) JP10.8@6255.56,9644.44 ; JP10.8@6228.69,9648.69 cw(c6201.37,9621.37) 6240,9621.37 cw(c6278.63,9621.37) JP10.8@6251.31,9648.69 ; U1.47@6274.31,8578.8 v1(6507,8578.8) ; U1.47@6299.98,8576.75 cw(c6304.94,8571.79) 6304.94,8578.8 cw(c6304.94,8585.82) U1.47@6299.98,8580.86 ; v1@6503.46,8575.27 ccw(c6494.93,8566.73) 6494.93,8578.8 ccw(c6494.93,8590.87) v1@6503.46,8582.34
  BottomLayer w6: v1@6202,9464 cw(c6202,9451.93) 6210.54,9460.46 cw(c6219.07,9469) v1@6207,9469 ; v1(6202,9469) 6506,9165 ; v1@6503.46,8582.34 ccw(c6494.93,8590.87) 6507,8590.87 ccw(c6519.07,8590.87) v1@6510.54,8582.34 ; v1(6507,8578.8) 6507,9165
101_T\X\R\S\T\: U1.64 U3.H9 | length 461.5
  TopLayer w6: U3.H9@5985.1,9277.41 cw(c5970.96,9277.41) 5980.96,9267.41 cw(c5990.96,9257.41) U3.H9@5990.96,9271.55 ; U3.H9@5990.96,9277.41 5971,9257.45 5971,9157 6127.65,9000.35 U1.64@6127.65,8922.31 ; U1.64@6125.6,8947.98 ccw(c6120.64,8952.94) 6127.65,8952.94 ccw(c6134.67,8952.94) U1.64@6129.71,8947.98
101_TCK: JP10.4 U3.E8 | length 1003.8
  TopLayer w6: U3.E8@5951.59,9389.66 cw(c5951.59,9375.52) 5961.59,9385.52 cw(c5971.59,9395.52) U3.E8@5957.45,9395.52 ; U3.E8@5951.59,9395.52 v1(5970.11,9377) ; v1@5965.11,9377 ccw(c5953.04,9377) 5961.57,9385.54 ccw(c5970.11,9394.07) v1@5970.11,9382 ; v1(6057,9377) 6229,9377 6440,9588 JP10.4@6440,9660 ; v1@6060.54,9373.46 cw(c6069.07,9364.93) 6069.07,9377 cw(c6069.07,9389.07) v1@6060.54,9380.54 ; JP10.4@6420.2,9640.2 cw(c6372.4,9592.4) 6440,9592.4 cw(c6507.6,9592.4) JP10.4@6459.8,9640.2 ; JP10.4@6424.44,9644.44 cw(c6386.89,9606.89) 6440,9606.89 cw(c6493.11,9606.89) JP10.4@6455.56,9644.44 ; JP10.4@6428.69,9648.69 cw(c6401.37,9621.37) 6440,9621.37 cw(c6478.63,9621.37) JP10.4@6451.31,9648.69
  BottomLayer w6: v1(5970.11,9377) v1(6057,9377) ; v1@5973.65,9373.46 cw(c5982.18,9364.93) 5982.18,9377 cw(c5982.18,9389.07) v1@5973.65,9380.54 ; v1@6053.46,9373.46 ccw(c6044.93,9364.93) 6044.93,9377 ccw(c6044.93,9389.07) v1@6053.46,9380.54
101_TDI: JP10.6 U3.D10 | length 727.6
  TopLayer w6: U3.D10@6030.33,9434.89 6203.89,9434.89 6340,9571 JP10.6@6340,9660 ; U3.D10@6034.47,9430.75 cw(c6044.47,9420.75) 6044.47,9434.89 cw(c6044.47,9449.03) U3.D10@6034.47,9439.03 ; JP10.6@6320.2,9640.2 cw(c6272.4,9592.4) 6340,9592.4 cw(c6407.6,9592.4) JP10.6@6359.8,9640.2 ; JP10.6@6324.44,9644.44 cw(c6286.89,9606.89) 6340,9606.89 cw(c6393.11,9606.89) JP10.6@6355.56,9644.44 ; JP10.6@6328.69,9648.69 cw(c6301.37,9621.37) 6340,9621.37 cw(c6378.63,9621.37) JP10.6@6351.31,9648.69
101_TDO: JP10.9 U3.B3 | length 817.7
  TopLayer w6: U3.B3@5754.74,9513.63 v1(5774.63,9533.52) ; U3.B3@5754.74,9519.49 ccw(c5754.74,9533.63) 5764.74,9523.63 ccw(c5774.74,9513.63) U3.B3@5760.6,9513.63 ; v1@5769.63,9533.52 cw(c5757.56,9533.52) 5766.09,9524.98 cw(c5774.63,9516.45) v1@5774.63,9528.52
  BottomLayer w6: v1@5771.09,9537.06 ccw(c5762.56,9545.59) 5774.63,9545.59 ccw(c5786.7,9545.59) v1@5778.17,9537.06 ; v1(5774.63,9533.52) 5774.63,9567.63 5967,9760 JP10.9@6140,9760 ; JP10.9@6120.2,9740.2 ccw(c6072.4,9692.4) 6072.4,9760 ccw(c6072.4,9827.6) JP10.9@6120.2,9779.8 ; JP10.9@6124.44,9744.44 ccw(c6086.89,9706.89) 6086.89,9760 ccw(c6086.89,9813.11) JP10.9@6124.44,9775.56 ; JP10.9@6128.69,9748.69 ccw(c6101.37,9721.37) 6101.37,9760 ccw(c6101.37,9798.63) JP10.9@6128.69,9771.31
101_TMS: JP10.2 U3.D8 | length 1077.3
  TopLayer w6: U3.D8@5951.59,9429.03 cw(c5951.59,9414.89) 5961.59,9424.89 cw(c5971.59,9434.89) U3.D8@5957.45,9434.89 ; U3.D8@5951.59,9434.89 5971.48,9415 6232,9415 6389,9572 6389,9682 6418,9711 6489,9711 JP10.2@6540,9660 ; JP10.2@6512,9660 ccw(c6444.4,9660) 6492.2,9707.8 ccw(c6540,9755.6) JP10.2@6540,9688 ; JP10.2@6518,9660 ccw(c6464.89,9660) 6502.44,9697.56 ccw(c6540,9735.11) JP10.2@6540,9682 ; JP10.2@6524,9660 ccw(c6485.37,9660) 6512.69,9687.31 ccw(c6540,9714.63) JP10.2@6540,9676
101_TXCKSEL: U1.56 U3.E10 | length 1032.3
  TopLayer w6: U3.E10@6030.33,9395.52 v1(6084.48,9395.52) ; U3.E10@6034.47,9391.38 cw(c6044.47,9381.38) 6044.47,9395.52 cw(c6044.47,9409.66) U3.E10@6034.47,9399.66 ; v1@6080.94,9391.98 ccw(c6072.41,9383.45) 6072.41,9395.52 ccw(c6072.41,9407.59) v1@6080.94,9399.06 ; U1.56@6274.31,8755.97 v1(6381,8755.97) ; U1.56@6299.98,8753.91 cw(c6304.94,8748.95) 6304.94,8755.97 cw(c6304.94,8762.98) U1.56@6299.98,8758.02 ; v1@6377.46,8752.43 ccw(c6368.93,8743.9) 6368.93,8755.97 ccw(c6368.93,8768.04) v1@6377.46,8759.5
  BottomLayer w6: v1@6084.48,9390.52 cw(c6084.48,9378.45) 6093.02,9386.98 cw(c6101.55,9395.52) v1@6089.48,9395.52 ; v1(6084.48,9395.52) 6381,9099 v1(6381,8755.97) ; v1@6377.46,8759.5 ccw(c6368.93,8768.04) 6381,8768.04 ccw(c6393.07,8768.04) v1@6384.54,8759.5
101_TXCLK: U1.66 U3.H8 | length 570.8
  TopLayer w6: v1(5933,9258.82) U3.H8@5951.59,9277.41 ; v1@5933,9263.82 ccw(c5933,9275.89) 5941.54,9267.35 ccw(c5950.07,9258.82) v1@5938,9258.82 ; U3.H8@5945.73,9277.41 cw(c5931.59,9277.41) 5941.59,9267.41 cw(c5951.59,9257.41) U3.H8@5951.59,9271.55 ; v1@6084.75,8962.18 cw(c6076.21,8953.65) 6088.28,8953.65 cw(c6100.35,8953.65) v1@6091.82,8962.18 ; U1.66@6086.23,8947.98 ccw(c6081.27,8952.94) 6088.28,8952.94 ccw(c6095.3,8952.94) U1.66@6090.34,8947.98 ; U1.66@6088.28,8922.31 v1(6088.28,8965.72)
  BottomLayer w6: v1@5929.46,9255.28 cw(c5920.93,9246.75) 5933,9246.75 cw(c5945.07,9246.75) v1@5936.54,9255.28 ; v1(5933,9258.82) 5933,9104 6007,9030 6066,9030 6088.28,9007.72 v1(6088.28,8965.72) ; v1@6084.75,8969.25 ccw(c6076.21,8977.79) 6088.28,8977.79 ccw(c6100.35,8977.79) v1@6091.82,8969.25
101_TXCLKO+: U1.62 U3.G9 | length 534.2
  TopLayer w6: U3.G9@5990.96,9310.92 cw(c5990.96,9296.78) 6000.96,9306.78 cw(c6010.96,9316.78) U3.G9@5996.82,9316.78 ; U3.G9@5990.96,9316.78 6011.74,9296 6069,9296 6167.02,9197.98 U1.62@6167.02,8922.31 ; U1.62@6164.97,8947.98 ccw(c6160.01,8952.94) 6167.02,8952.94 ccw(c6174.04,8952.94) U1.62@6169.08,8947.98
101_TXCLKO-: U1.61 U3.G10 | length 518.2
  TopLayer w6: U3.G10@6030.33,9316.78 6074.22,9316.78 6186.71,9204.29 U1.61@6186.71,8922.31 ; U3.G10@6034.47,9312.64 cw(c6044.47,9302.64) 6044.47,9316.78 cw(c6044.47,9330.92) U3.G10@6034.47,9320.92 ; U1.61@6184.65,8947.98 ccw(c6179.69,8952.94) 6186.71,8952.94 ccw(c6193.72,8952.94) U1.61@6188.76,8947.98
101_TXCT0: U1.82 U3.J5 | length 373.9
  TopLayer w6: U1.82@5771.27,8947.98 ccw(c5766.31,8952.94) 5773.32,8952.94 ccw(c5780.34,8952.94) U1.82@5775.38,8947.98 ; U1.82@5773.32,8922.31 5773.32,8961.32 5813,9001 5813,9217.56 U3.J5@5833.48,9238.04 ; U3.J5@5827.62,9238.04 cw(c5813.48,9238.04) 5823.48,9228.04 cw(c5833.48,9218.04) U3.J5@5833.48,9232.18
101_TXCT1: U1.73 U3.H5 | length 529.6
  TopLayer w6: v1(5813,9256.93) U3.H5@5833.48,9277.41 ; v1@5813,9261.93 ccw(c5813,9274) 5821.54,9265.46 ccw(c5830.07,9256.93) v1@5818,9256.93 ; U3.H5@5827.62,9277.41 cw(c5813.48,9277.41) 5823.48,9267.41 cw(c5833.48,9257.41) U3.H5@5833.48,9271.55 ; v1@5946.95,8997.98 cw(c5938.42,8989.44) 5950.49,8989.44 cw(c5962.56,8989.44) v1@5954.02,8997.98 ; U1.73@5948.43,8947.98 ccw(c5943.47,8952.94) 5950.49,8952.94 ccw(c5957.5,8952.94) U1.73@5952.54,8947.98 ; U1.73@5950.49,8922.31 v1(5950.49,9001.51)
  BottomLayer w6: v1@5809.46,9253.39 cw(c5800.93,9244.86) 5813,9244.86 cw(c5825.07,9244.86) v1@5816.54,9253.39 ; v1(5813,9256.93) 5813,9139 v1(5950.49,9001.51) ; v1@5945.49,9001.51 ccw(c5933.42,9001.51) 5941.95,9010.05 ccw(c5950.49,9018.58) v1@5950.49,9006.51
101_TXD0: U1.65 U3.J8 | length 429.1
  TopLayer w6: U3.J8@5945.73,9238.04 cw(c5931.59,9238.04) 5941.59,9228.04 cw(c5951.59,9218.04) U3.J8@5951.59,9232.18 ; U3.J8@5951.59,9238.04 5933,9219.45 5933,9169 6107.97,8994.03 U1.65@6107.97,8922.31 ; U1.65@6105.91,8947.98 ccw(c6100.95,8952.94) 6107.97,8952.94 ccw(c6114.98,8952.94) U1.65@6110.02,8947.98
101_TXD1: U1.75 U3.K7 | length 310.1
  TopLayer w6: U3.K7@5908.08,9194.53 cw(c5900.74,9187.19) 5911.12,9187.19 ; U1.75@5909.06,8947.98 ccw(c5904.1,8952.94) 5911.12,8952.94 ccw(c5918.13,8952.94) U1.75@5913.17,8947.98 ; U1.75@5911.12,8922.31 5911.12,9197.57 U3.K7@5912.22,9198.67 ; 5911.12,9181.86 cw(c5929.03,9181.86) U3.K7@5916.36,9194.53
101_TXD2: U1.76 U3.J7 | length 357.6
  TopLayer w6: U1.76@5889.38,8947.98 ccw(c5884.42,8952.94) 5891.43,8952.94 ccw(c5898.45,8952.94) U1.76@5893.49,8947.98 ; U1.76@5891.43,8922.31 5891.43,9217.25 U3.J7@5912.22,9238.04 ; U3.J7@5906.36,9238.04 cw(c5892.22,9238.04) 5902.22,9228.04 cw(c5912.22,9218.04) U3.J7@5912.22,9232.18
101_TXD3: U1.67 U3.H7 | length 575.9
  TopLayer w6: v1(5893,9258.19) U3.H7@5912.22,9277.41 ; v1@5893,9263.19 ccw(c5893,9275.26) 5901.54,9266.72 ccw(c5910.07,9258.19) v1@5898,9258.19 ; U3.H7@5906.36,9277.41 cw(c5892.22,9277.41) 5902.22,9267.41 cw(c5912.22,9257.41) U3.H7@5912.22,9271.55 ; v1@6054,9002 cw(c6054,8989.93) 6062.54,8998.46 cw(c6071.07,9007) v1@6059,9007 ; v1(6054,9007) 6068.6,8992.4 U1.67@6068.6,8922.31 ; U1.67@6066.54,8947.98 ccw(c6061.58,8952.94) 6068.6,8952.94 ccw(c6075.61,8952.94) U1.67@6070.65,8947.98
  BottomLayer w6: v1@5889.46,9254.65 cw(c5880.93,9246.12) 5893,9246.12 cw(c5905.07,9246.12) v1@5896.54,9254.65 ; v1(5893,9258.19) 5893,9115 6001,9007 v1(6054,9007) ; v1@6050.46,9003.46 ccw(c6041.93,8994.93) 6041.93,9007 ccw(c6041.93,9019.07) v1@6050.46,9010.54
101_TXD4: U1.77 U3.K6 | length 310.1
  TopLayer w6: U3.K6@5868.71,9194.53 cw(c5861.37,9187.19) 5871.75,9187.19 ; U1.77@5869.69,8947.98 ccw(c5864.73,8952.94) 5871.75,8952.94 ccw(c5878.76,8952.94) U1.77@5873.8,8947.98 ; U1.77@5871.75,8922.31 5871.75,9197.57 U3.K6@5872.85,9198.67 ; 5871.75,9181.86 cw(c5889.66,9181.86) U3.K6@5876.99,9194.53
101_TXD5: U1.78 U3.J6 | length 357.6
  TopLayer w6: U1.78@5850.01,8947.98 ccw(c5845.05,8952.94) 5852.06,8952.94 ccw(c5859.08,8952.94) U1.78@5854.12,8947.98 ; U1.78@5852.06,8922.31 5852.06,9217.25 U3.J6@5872.85,9238.04 ; U3.J6@5866.99,9238.04 cw(c5852.85,9238.04) 5862.85,9228.04 cw(c5872.85,9218.04) U3.J6@5872.85,9232.18
101_TXD6: U1.68 U3.H6 | length 575.8
  TopLayer w6: v1(5853,9257.56) U3.H6@5872.85,9277.41 ; v1@5853,9262.56 ccw(c5853,9274.63) 5861.54,9266.09 ccw(c5870.07,9257.56) v1@5858,9257.56 ; U3.H6@5866.99,9277.41 cw(c5852.85,9277.41) 5862.85,9267.41 cw(c5872.85,9257.41) U3.H6@5872.85,9271.55 ; v1@6038,8975 cw(c6038,8962.93) 6046.54,8971.46 cw(c6055.07,8980) v1@6043,8980 ; v1(6038,8980) 6048.91,8969.09 U1.68@6048.91,8922.31 ; U1.68@6046.86,8947.98 ccw(c6041.9,8952.94) 6048.91,8952.94 ccw(c6055.93,8952.94) U1.68@6050.97,8947.98
  BottomLayer w6: v1@5849.46,9254.02 cw(c5840.93,9245.49) 5853,9245.49 cw(c5865.07,9245.49) v1@5856.54,9254.02 ; v1(5853,9257.56) 5853,9127 6000,8980 v1(6038,8980) ; v1@6034.46,8976.46 ccw(c6025.93,8967.93) 6025.93,8980 ccw(c6025.93,8992.07) v1@6034.46,8983.54
101_TXD7: U1.79 U3.K5 | length 309.1
  TopLayer w6: U3.K5@5829.34,9194.53 cw(c5819.34,9184.53) 5833.48,9184.53 cw(c5847.62,9184.53) U3.K5@5837.62,9194.53 ; U1.79@5830.32,8947.98 ccw(c5822.7,8955.6) 5833.48,8955.6 ; U1.79@5832.38,8922.31 5833.48,8923.41 U3.K5@5833.48,9198.67 U3.K5@5832.38,9197.57
101_TXMODE0: U1.53 U3.B6 | length 1416.3
  TopLayer w6: U3.B6@5872.85,9507.77 cw(c5872.85,9493.63) 5882.85,9503.63 cw(c5892.85,9513.63) U3.B6@5878.71,9513.63 ; U3.B6@5872.85,9513.63 v1(5891.48,9495) ; v1@5886.48,9495 ccw(c5874.41,9495) 5882.94,9503.54 ccw(c5891.48,9512.07) v1@5891.48,9500 ; U1.53@6274.31,8696.91 v1(6435,8696.91) ; U1.53@6299.98,8694.86 cw(c6304.94,8689.9) 6304.94,8696.91 cw(c6304.94,8703.93) U1.53@6299.98,8698.97 ; v1@6431.46,8693.38 ccw(c6422.93,8684.84) 6422.93,8696.91 ccw(c6422.93,8708.98) v1@6431.46,8700.45
  BottomLayer w6: v1@5891.48,9490 cw(c5891.48,9477.93) 5900.02,9486.46 cw(c5908.55,9495) v1@5896.48,9495 ; v1(5891.48,9495) 5910.48,9476 5982,9476 6007,9451 6101,9451 6435,9117 v1(6435,8696.91) ; v1@6431.46,8700.45 ccw(c6422.93,8708.98) 6435,8708.98 ccw(c6447.07,8708.98) v1@6438.54,8700.45
101_TXMODE1: U1.46 U3.A6 | length 1820.1
  TopLayer w6: U3.A6@5868.71,9557.14 ccw(c5858.71,9567.14) 5872.85,9567.14 ccw(c5886.99,9567.14) U3.A6@5876.99,9557.14 ; v1@5869.31,9574.31 cw(c5860.78,9565.78) 5872.85,9565.78 cw(c5884.92,9565.78) v1@5876.39,9574.31 ; U3.A6@5872.85,9553 v1(5872.85,9577.85) ; U1.46@6274.31,8559.12 v1(6525,8559.12) ; U1.46@6299.98,8557.06 cw(c6304.94,8552.1) 6304.94,8559.12 cw(c6304.94,8566.13) U1.46@6299.98,8561.17 ; v1@6521.46,8555.58 ccw(c6512.93,8547.05) 6512.93,8559.12 ccw(c6512.93,8571.19) v1@6521.46,8562.65
  BottomLayer w6: v1(5872.85,9577.85) 5898,9577.85 5965.85,9510 6191,9510 6525,9176 v1(6525,8559.12) ; v1@5876.39,9574.31 cw(c5884.92,9565.78) 5884.92,9577.85 cw(c5884.92,9589.92) v1@5876.39,9581.39 ; v1@6521.46,8562.65 ccw(c6512.93,8571.19) 6525,8571.19 ccw(c6537.07,8571.19) v1@6528.54,8562.65
101_TXOP: U1.59 U3.G8 | length 886.4
  TopLayer w6: U3.G8@5951.59,9310.92 cw(c5951.59,9296.78) 5961.59,9306.78 cw(c5971.59,9316.78) U3.G8@5957.45,9316.78 ; U3.G8@5951.59,9316.78 v1(5970.37,9298) ; v1@5965.37,9298 ccw(c5953.3,9298) 5961.83,9306.54 ccw(c5970.37,9315.07) v1@5970.37,9303 ; U1.59@6274.31,8815.02 v1(6316.02,8815.02) ; U1.59@6299.98,8812.97 cw(c6304.94,8808.01) 6304.94,8815.02 cw(c6304.94,8822.04) U1.59@6299.98,8817.08 ; v1@6312.49,8811.49 ccw(c6303.95,8802.95) 6303.95,8815.02 ccw(c6303.95,8827.09) v1@6312.49,8818.56
  BottomLayer w6: v1(5970.37,9298) 6095,9298 6328,9065 6328,8827 v1(6316.02,8815.02) ; v1@5973.91,9294.46 cw(c5982.44,9285.93) 5982.44,9298 cw(c5982.44,9310.07) v1@5973.91,9301.54 ; v1@6316.02,8820.02 ccw(c6316.02,8832.09) 6324.56,8823.56 ccw(c6333.09,8815.02) v1@6321.02,8815.02
101_TXPER: U1.58 U3.F8 | length 966.4
  TopLayer w6: U3.F8@5951.59,9350.29 cw(c5951.59,9336.15) 5961.59,9346.15 cw(c5971.59,9356.15) U3.F8@5957.45,9356.15 ; U3.F8@5951.59,9356.15 v1(5971.74,9336) ; v1@5966.74,9336 ccw(c5954.67,9336) 5963.2,9344.54 ccw(c5971.74,9353.07) v1@5971.74,9341 ; U1.58@6274.31,8795.34 v1(6345,8795.34) ; U1.58@6299.98,8793.28 cw(c6304.94,8788.32) 6304.94,8795.34 cw(c6304.94,8802.35) U1.58@6299.98,8797.39 ; v1@6341.46,8791.8 ccw(c6332.93,8783.27) 6332.93,8795.34 ccw(c6332.93,8807.41) v1@6341.46,8798.87
  BottomLayer w6: v1@5971.74,9331 cw(c5971.74,9318.93) 5980.28,9327.46 cw(c5988.81,9336) v1@5976.74,9336 ; v1(5971.74,9336) 5990.74,9317 6098,9317 6345,9070 v1(6345,8795.34) ; v1@6341.46,8798.87 ccw(c6332.93,8807.41) 6345,8807.41 ccw(c6357.07,8807.41) v1@6348.54,8798.87
101_TXRATE: U1.50 U3.B5 | length 1550.2
  TopLayer w6: U3.B5@5833.48,9513.63 v1(5853.7,9533.85) ; U3.B5@5833.48,9519.49 ccw(c5833.48,9533.63) 5843.48,9523.63 ccw(c5853.48,9513.63) U3.B5@5839.34,9513.63 ; v1@5848.7,9533.85 cw(c5836.63,9533.85) 5845.17,9525.31 cw(c5853.7,9516.78) v1@5853.7,9528.85 ; U1.50@6274.31,8637.86 v1(6346.86,8637.86) ; U1.50@6299.98,8635.8 cw(c6304.94,8630.84) 6304.94,8637.86 cw(c6304.94,8644.87) U1.50@6299.98,8639.91 ; v1@6343.32,8634.32 ccw(c6334.79,8625.79) 6334.79,8637.86 ccw(c6334.79,8649.93) v1@6343.32,8641.39
  BottomLayer w6: v1(5853.7,9533.85) 5883.15,9533.85 5922,9495 5987,9495 6018,9464 6110,9464 6452,9122 6452,8669 6420.86,8637.86 v1(6346.86,8637.86) ; v1@5857.24,9530.31 cw(c5865.77,9521.78) 5865.77,9533.85 cw(c5865.77,9545.92) v1@5857.24,9537.39 ; v1@6350.39,8634.32 cw(c6358.93,8625.79) 6358.93,8637.86 cw(c6358.93,8649.93) v1@6350.39,8641.39
AGND: C85.1 C87.1 C88.1 C90.1 FB2.1 J1.2 R29.1 U10.32 U10.33 | length 1206.4
  TopLayer w12: R29.1@7390.32,8634.89 cw(c7366.96,8611.53) 7400,8611.53 cw(c7433.04,8611.53) R29.1@7409.68,8634.89 ; v3@7395.76,8582.24 ccw(c7385.51,8592.49) 7400,8592.49 ccw(c7414.49,8592.49) v3@7404.24,8582.24 ; v3(7400,8578) R29.1@7400,8646.54 ; U10.33@7620,8607.87 7620,8661 v3(7639,8680) 7651.5,8667.5 U10.32@7651.5,8607.87 ; U10.33@7621.87,8649.21 cw(c7654.86,8649.21) v3@7631.53,8672.53 ; v3@7633,8680 cw(c7618.51,8680) 7628.76,8669.76 cw(c7639,8659.51) 7639,8674 cw(c7639,8659.51) 7649.24,8669.76 cw(c7659.49,8680) v3@7645,8680 ; v3@7634.76,8675.76 cw(c7594.35,8635.35) U10.32@7651.5,8635.35 ; v3@7643.24,8684.24 cw(c7623.32,8664.32) 7651.5,8664.32
  TopLayer w20: FB2.1@7313.15,8542.28 ccw(c7296.62,8558.81) 7320,8558.81 ccw(c7343.38,8558.81) FB2.1@7326.85,8542.28 ; FB2.1@7320,8533.46 v3(7320,8604)
  BottomLayer w12: C85.1@7390.32,8525.11 ccw(c7366.96,8548.47) 7400,8548.47 ccw(c7433.04,8548.47) C85.1@7409.68,8525.11 ; v3@7395.76,8573.76 cw(c7385.51,8563.51) 7400,8563.51 cw(c7414.49,8563.51) v3@7404.24,8573.76 ; C85.1@7400,8513.46 v3(7400,8578) ; C87.1@7610.32,8605.11 ccw(c7586.96,8628.47) 7620,8628.47 ccw(c7653.04,8628.47) C87.1@7629.68,8605.11 ; C87.1@7620,8593.46 7620,8661 v3(7639,8680) ; v3@7633,8680 cw(c7618.51,8680) 7628.76,8669.76 cw(c7639,8659.51) v3@7639,8674 ; C88.1@7730.32,8605.11 ccw(c7706.96,8628.47) 7740,8628.47 ccw(c7773.04,8628.47) C88.1@7749.68,8605.11 ; C88.1@7740,8593.46 7740,8669 v3(7758,8687) ; v3@7752,8687 cw(c7737.51,8687) 7747.76,8676.76 cw(c7758,8666.51) v3@7758,8681 ; v3@7818,8680 cw(c7818,8665.51) 7828.24,8675.76 cw(c7838.49,8686) v3@7824,8686 ; v3(7818,8686) 7840,8664 C90.1@7840,8593.46 ; C90.1@7830.32,8605.11 ccw(c7806.96,8628.47) 7840,8628.47 ccw(c7873.04,8628.47) C90.1@7849.68,8605.11
AOE#: R71.6 U1.234 U4.19 | length 2630.1
  TopLayer w6: U1.234@6066.54,7560.02 cw(c6061.58,7555.06) 6068.6,7555.06 cw(c6075.61,7555.06) U1.234@6070.65,7560.02 ; U1.234@6068.6,7585.69 6068.6,7530.6 5938,7400 5938,7131 6005,7064 6561,7064 6603,7022 v1(7366,7022) ; v1@6748.13,6890.13 cw(c6739.6,6881.6) 6751.67,6881.6 cw(c6763.74,6881.6) v1@6755.21,6890.13 ; U4.19@6749.62,6869.52 ccw(c6744.66,6874.48) 6751.67,6874.48 ccw(c6758.68,6874.48) U4.19@6753.72,6869.52 ; U4.19@6751.67,6834 v1(6751.67,6893.67) ; v1@6842.46,7018.46 ccw(c6833.93,7009.93) 6833.93,7022 ccw(c6833.93,7034.07) v1@6842.46,7025.54 ; v1@6849.54,7018.46 cw(c6858.07,7009.93) 6858.07,7022 cw(c6858.07,7034.07) v1@6849.54,7025.54 ; v1@7362.46,7018.46 ccw(c7353.93,7009.93) 7353.93,7022 ccw(c7353.93,7034.07) v1@7362.46,7025.54
  BottomLayer w6: v1@6748.13,6897.21 ccw(c6739.6,6905.74) 6751.67,6905.74 ccw(c6763.74,6905.74) v1@6755.21,6897.21 ; v1(6751.67,6893.67) 6751.67,6948.67 6825,7022 v1(6846,7022) ; v1@6842.46,7018.46 ccw(c6833.93,7009.93) 6833.93,7022 ccw(c6833.93,7034.07) v1@6842.46,7025.54 ; v1(7366,7022) 7466,7122 R71.6@7555.84,7122 ; v1@7366,7027 ccw(c7366,7039.07) 7374.54,7030.54 ccw(c7383.07,7022) v1@7371,7022 ; R71.6@7543.1,7117.76 ccw(c7532.86,7107.51) 7532.86,7122 ccw(c7532.86,7136.49) R71.6@7543.1,7126.24
ARE#: R71.5 U1.233 U2.28 U4.18 | length 3664.5
  TopLayer w6: U2.28@5170.72,6807.7 v1(5223.7,6807.7) ; U2.28@5206.24,6805.65 cw(c5211.2,6800.69) 5211.2,6807.7 cw(c5211.2,6814.71) U2.28@5206.24,6809.75 ; v1@5220.16,6804.16 ccw(c5211.63,6795.63) 5211.63,6807.7 ccw(c5211.63,6819.77) v1@5220.16,6811.24 ; v1@5960,7044 ccw(c5947.93,7044) 5956.46,7052.54 ccw(c5965,7061.07) v1@5965,7049 ; v1@5968.54,7040.46 cw(c5977.07,7031.93) 5977.07,7044 cw(c5977.07,7056.07) v1@5968.54,7047.54 ; U1.233@6046.86,7560.02 cw(c6041.9,7555.06) 6048.91,7555.06 cw(c6055.93,7555.06) U1.233@6050.97,7560.02 ; U1.233@6048.91,7585.69 6048.91,7531.91 5926,7409 5926,7083 v1(5965,7044) 6546,7044 6587,7003 v1(7393,7003) ; v1@6767.82,6911.82 cw(c6759.28,6903.28) 6771.36,6903.28 cw(c6783.43,6903.28) v1@6774.89,6911.82 ; U4.18@6769.3,6869.52 ccw(c6764.34,6874.48) 6771.36,6874.48 ccw(c6778.37,6874.48) U4.18@6773.41,6869.52 ; U4.18@6771.35,6834 v1(6771.35,6915.35) ; v1@6869.46,6999.46 ccw(c6860.93,6990.93) 6860.93,7003 ccw(c6860.93,7015.07) v1@6869.46,7006.54 ; v1@6876.54,6999.46 cw(c6885.07,6990.93) 6885.07,7003 cw(c6885.07,7015.07) v1@6876.54,7006.54 ; v1@7389.46,6999.46 ccw(c7380.93,6990.93) 7380.93,7003 ccw(c7380.93,7015.07) v1@7389.46,7006.54
  BottomLayer w6: v1(5223.7,6807.7) 5728.7,6807.7 v1(5965,7044) ; v1@5227.24,6804.16 cw(c5235.77,6795.63) 5235.77,6807.7 cw(c5235.77,6819.77) v1@5227.24,6811.24 ; v1@5960,7044 cw(c5947.93,7044) 5956.46,7035.46 cw(c5965,7026.93) v1@5965,7039 ; v1@6767.82,6918.89 ccw(c6759.28,6927.43) 6771.36,6927.43 ccw(c6783.43,6927.43) v1@6774.89,6918.89 ; v1(6771.35,6915.35) 6771.35,6947.35 6827,7003 v1(6873,7003) ; v1@6869.46,6999.46 ccw(c6860.93,6990.93) 6860.93,7003 ccw(c6860.93,7015.07) v1@6869.46,7006.54 ; v1(7393,7003) 7476,7086 R71.5@7555.84,7086 ; v1@7393,7008 ccw(c7393,7020.07) 7401.54,7011.54 ccw(c7410.07,7003) v1@7398,7003 ; R71.5@7543.1,7081.76 ccw(c7532.86,7071.51) 7532.86,7086 ccw(c7532.86,7100.49) R71.5@7543.1,7090.24
AS_CONFDN: JP11.3 R26.1 U1.145 | length 3486.3
  TopLayer w6: U1.145@4937.69,8362.27 v1(6221.73,8362.27) ; U1.145@4963.37,8360.21 cw(c4968.33,8355.25) 4968.33,8362.27 cw(c4968.33,8369.28) U1.145@4963.37,8364.32 ; v1@6218.2,8358.73 ccw(c6209.66,8350.2) 6209.66,8362.27 ccw(c6209.66,8374.34) v1@6218.2,8365.8 ; JP11.3@6901.45,7920.97 ccw(c6825.78,8006.53) R26.1@6940,8006.54 6940,7920 JP11.3@6920,7900 ; JP11.3@6905.43,7916.48 ccw(c6837.56,7993.21) R26.1@6940,7993.21 ; JP11.3@6909.4,7911.99 ccw(c6849.34,7979.9) 6940,7979.9 ; JP11.3@6913.38,7907.49 ccw(c6861.11,7966.58) 6940,7966.58 ; JP11.3@6917.35,7903 ccw(c6872.89,7953.27) 6940,7953.27 ; JP11.3@6921.32,7898.5 ccw(c6884.67,7939.95) 6940,7939.95 ; JP11.3@6925.3,7894.01 ccw(c6896.45,7926.63) 6940,7926.63 ; R26.1@6928.2,7992.77 cw(c6899.72,7964.29) 6940,7964.29 cw(c6980.28,7964.29) R26.1@6951.8,7992.77 ; R26.1@6932.44,7997.01 cw(c6914.2,7978.77) 6940,7978.77 cw(c6965.8,7978.77) R26.1@6947.56,7997.01
  BottomLayer w6: v1@6221.73,8357.27 cw(c6221.73,8345.2) 6230.27,8353.73 cw(c6238.8,8362.27) v1@6226.73,8362.27 ; v1(6221.73,8362.27) 6554,8030 6554,7777 6589,7742 6844,7742 6870,7768 6870,7850 JP11.3@6920,7900 ; JP11.3@6892,7900 cw(c6824.4,7900) 6872.2,7852.2 cw(c6920,7804.4) JP11.3@6920,7872 ; JP11.3@6898,7900 cw(c6844.89,7900) 6882.44,7862.44 cw(c6920,7824.89) JP11.3@6920,7878 ; JP11.3@6904,7900 cw(c6865.37,7900) 6892.69,7872.69 cw(c6920,7845.37) JP11.3@6920,7884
